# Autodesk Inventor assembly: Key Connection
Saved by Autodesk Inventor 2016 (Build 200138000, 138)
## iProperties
Created: 2015-08
Part Number: Key Connection
Document SubType Name: Assembly
Designer: Ugljesa
Mass: 5.68026 g
Surface Area: 5.14753 cm^2
Volume: 0.7236 cm^3
Density: 7.85 g/cm^3
ClientObjectVersion: 1
Author: Ugljesa
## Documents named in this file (2)
- C:\Users\Ugljesa\Desktop\Turbokompr\Sklop turbokompresora\Design Accelerator\Key Connection3.iam
- C:\Users\Ugljesa\Documents\Inventor\Content Center Files\R2016\en-US\ISO 2491 - A\ISO 2491 - A  8 x 5 x 20.ipt
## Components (1 placed, 1 different names)
1. ISO 2491 A A  8 x 5 x 20:1
